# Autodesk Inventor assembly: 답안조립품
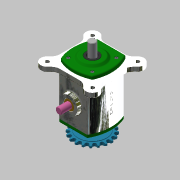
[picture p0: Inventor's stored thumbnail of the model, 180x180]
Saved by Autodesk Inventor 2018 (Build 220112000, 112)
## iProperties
Created: 2022-01
Part Number: 답안조립품
Material: 일반
Document SubType Name: Assembly
Designer: home
Author: home
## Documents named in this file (13)
- C:\Users\home\Desktop\720106V1025\답안조립품.iam
- C:\Users\home\Desktop\720106V1025\본체.ipt
- C:\Users\home\Desktop\720106V1025\커버.ipt
- C:\Users\home\Desktop\720106V1025\오일 실 17 x 30 x 8.ipt
- C:\Users\home\Desktop\720106V1025\볼트 M4 x 12.ipt
- C:\Users\home\Desktop\720106V1025\베어링 6203.ipt
- C:\Users\home\Desktop\720106V1025\편심축.ipt
- C:\Users\home\Desktop\720106V1025\슬라이더.ipt
- C:\Users\home\Desktop\720106V1025\부시.ipt
- C:\Users\home\Desktop\720106V1025\키 5 x 5.ipt
- C:\Users\home\Desktop\720106V1025\스프로킷.ipt
- C:\Users\home\Desktop\720106V1025\육각머리볼트 M4.ipt
- C:\Users\home\Desktop\720106V1025\와셔 4 x 20.ipt
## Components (8 placed, 1 different names)
1. M4x0.7x12:1
2. M4x0.7x12:2
3. M4x0.7x12:3
4. M4x0.7x12:4
5. M4x0.7x12:5
6. M4x0.7x12:6
7. M4x0.7x12:7
8. M4x0.7x12:8
